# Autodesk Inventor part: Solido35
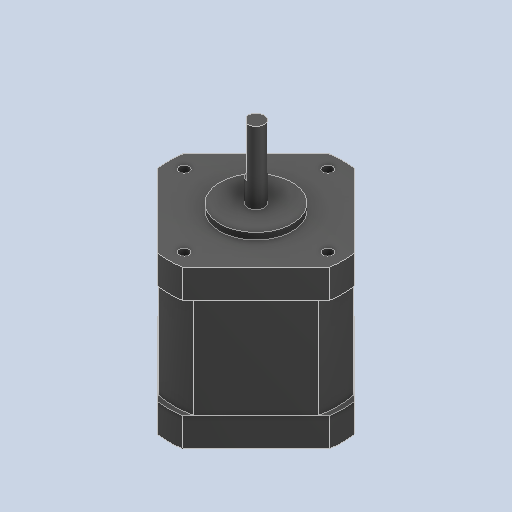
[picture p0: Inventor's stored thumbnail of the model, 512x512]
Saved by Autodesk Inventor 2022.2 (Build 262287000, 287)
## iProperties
Created: 2024-10
Part Number: Solido35
Material: Acciaio
Document SubType Name: Modeling
Designer: 18907419
Density: 7.85 g/cm^3
Appearance: Default
Author: 18907419
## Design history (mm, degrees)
feature "Solido35"
node "Solido1"
